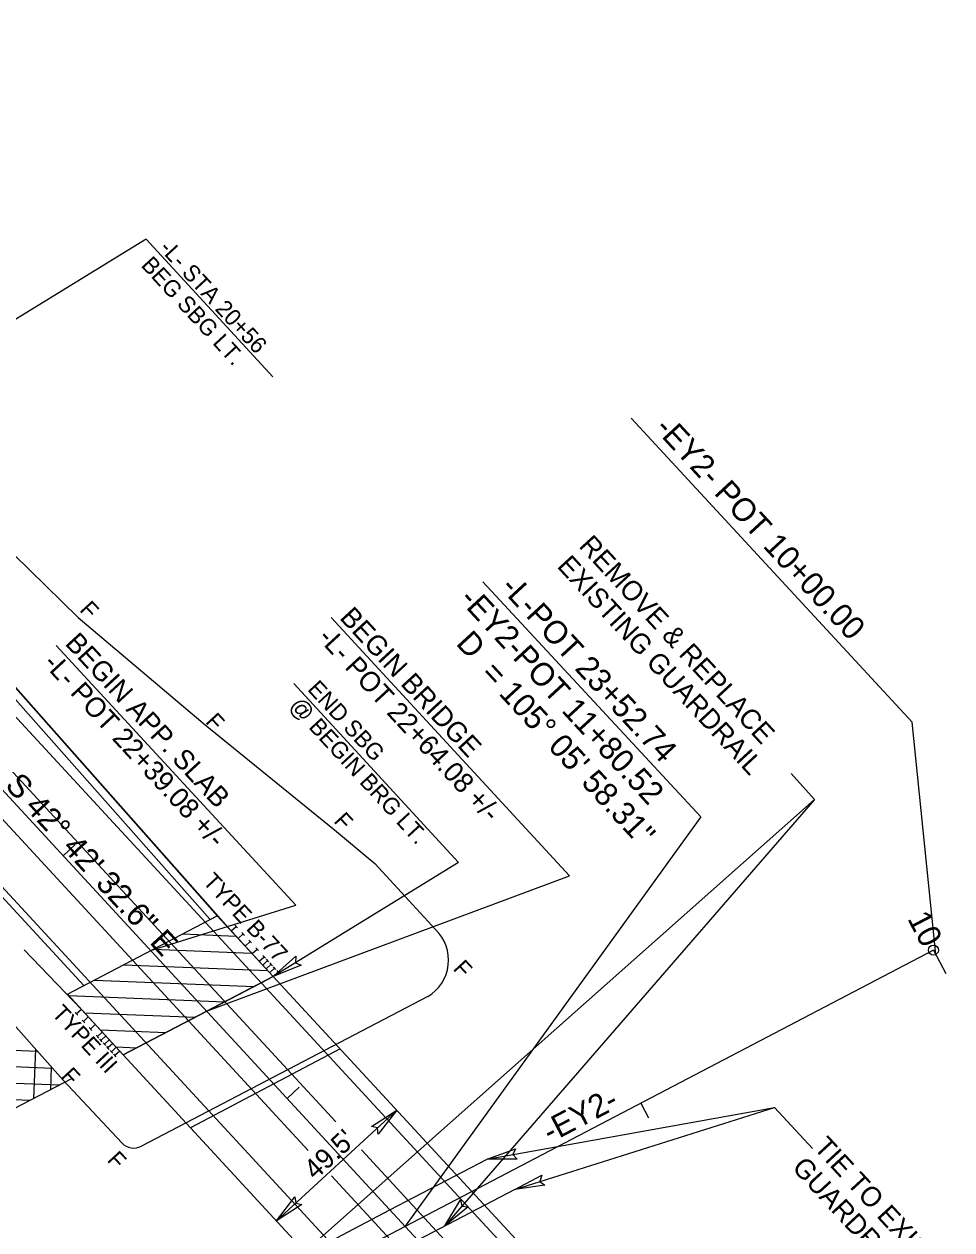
# Model space of a CAD drawing. Extents: x 1702862 to 1704514, y 793768 to 796215.
# Drawn here: x 1703456.2 to 1703737.1, y 794966.9 to 795332.1 of the extents above; entities that cross this region are included whole.
import ezdxf

# ---------------------------------------------------------------- set-up
doc = ezdxf.new("R2010")
doc.units = 0
for name, color, linetype in [('Exist Horizontal Alignment', 7, 'Continuous'), ('Exist Horizontal Alignment Direction Label', 7, 'Continuous'), ('Exist Horizontal Alignment Station Label', 7, 'Continuous'), ('Exist Horizontal Alignment Tick Label', 7, 'Continuous'), ('Exist Horizontal Alignment Tick Large', 7, 'Continuous'), ('Exist Horizontal Alignment Tick Small', 7, 'Continuous'), ('Prop Approach Slab', 7, 'Continuous'), ('Prop Conc 2ft 6in Curb and Gutter', 7, 'Continuous'), ('Prop Conc Shoulder Berm Gutter', 7, 'Continuous'), ('Prop Dimension', 7, 'Continuous'), ('Prop Dimension Text', 7, 'Continuous'), ('Prop DSN Text', 7, 'Continuous'), ('Prop EOT', 7, 'Continuous'), ('Prop Guardrail', 7, 'Continuous'), ('Prop Guardrail Anchor Unit CELL', 7, 'Continuous'), ('Prop Horizontal Alignment', 7, 'Continuous'), ('Prop Horizontal Alignment Direction Label', 7, 'Continuous'), ('Prop Horizontal Alignment Station Label', 7, 'Continuous'), ('Prop Horizontal Alignment Tick Small', 7, 'Continuous'), ('Prop Lane Lines', 7, 'Continuous'), ('Prop Leader Line Medium', 7, 'Continuous'), ('Prop Paved Shoulder', 7, 'Continuous'), ('Prop Rem of Exist Asph Pvmt', 7, 'Continuous'), ('Prop Roadway Bridge', 7, 'Continuous'), ('Prop SS Fill Line', 7, 'Continuous'), ('Prop SS Misc', 7, 'Continuous'), ('Prop Structure Anchor Unit CELL', 7, 'Continuous'), ('Prop Terminator CELL', 7, 'Continuous')]:
    doc.layers.add(name, color=color, linetype=linetype)

msp = doc.modelspace()

# ---------------------------------------------------------------- linework, layer by layer
at = {"layer": 'Exist Horizontal Alignment'}
msp.add_line((1703731.56, 795051.6), (1703391.21, 794873.6), dxfattribs=at)
at = {"layer": 'Exist Horizontal Alignment Station Label'}
for p, q in [((1703595.08, 795163.16), (1703661.15, 795092.04)), ((1703661.15, 795092.04), (1703571.59, 794967.94))]:
    msp.add_line(p, q, dxfattribs=at)
msp.add_lwpolyline([(1703732.26, 795050.27), (1703725.12, 795120.64), (1703640.05, 795212.74)], dxfattribs=at)
msp.add_circle((1703731.56, 795051.6), 1.5, dxfattribs=at)
at = {"layer": 'Exist Horizontal Alignment Tick Large'}
msp.add_line((1703731.56, 795051.6), (1703735.27, 795044.51), dxfattribs=at)
at = {"layer": 'Exist Horizontal Alignment Tick Small'}
msp.add_line((1703642.95, 795005.26), (1703645.26, 795000.83), dxfattribs=at)
at = {"layer": 'Prop Approach Slab'}
for p, q in [((1703469.28, 795038.24), (1703514.68, 795062.03)), ((1703514.68, 795062.03), (1703531.64, 795043.66)), ((1703504.12, 795056.5), (1703520.39, 795055.85)), ((1703495.25, 795051.85), (1703525.19, 795050.65)), ((1703486.37, 795047.2), (1703529.98, 795045.45)), ((1703477.5, 795042.55), (1703525.83, 795040.62)), ((1703486.23, 795019.87), (1703530.26, 795042.94)), ((1703486.23, 795019.87), (1703469.28, 795038.24)), ((1703469.63, 795037.86), (1703516.96, 795035.97)), ((1703474.43, 795032.66), (1703508.08, 795031.32)), ((1703479.22, 795027.47), (1703499.21, 795026.67)), ((1703484.02, 795022.27), (1703490.33, 795022.02))]:
    msp.add_line(p, q, dxfattribs=at)
msp.add_lwpolyline([(1703514.68, 795062.03), (1703531.64, 795043.66), (1703486.23, 795019.87), (1703469.28, 795038.24)], close=True, dxfattribs=at)
at = {"layer": 'Prop Conc 2ft 6in Curb and Gutter'}
msp.add_line((1703417.51, 795102.43), (1703474.32, 795040.89), dxfattribs=at)
at = {"layer": 'Prop Conc Shoulder Berm Gutter'}
msp.add_line((1703389.53, 795203.37), (1703514.68, 795062.03), dxfattribs=at)
at = {"layer": 'Prop Dimension'}
msp.add_line((1703532.64, 794969.6), (1703569.01, 795003.17), dxfattribs=at)
at = {"layer": 'Prop EOT'}
for p, q in [((1703259.9, 795332.15), (1703737.14, 794815.13)), ((1703418.98, 795103.79), (1703631.9, 794873.13))]:
    msp.add_line(p, q, dxfattribs=at)
msp.add_lwpolyline([(1703551.93, 795021.68), (1703506.62, 794997.79)], dxfattribs=at)
at = {"layer": 'Prop Guardrail'}
for p, q in [((1703518.92, 795057.44), (1703389.53, 795203.37)), ((1703456.19, 795051.68), (1703473.52, 795033.65)), ((1703566.95, 794972.97), (1703596.4, 794988.25)), ((1703604.81, 794979.13), (1703575.44, 794963.77)), ((1703492.38, 794933.6), (1703566.95, 794972.97))]:
    msp.add_line(p, q, dxfattribs=at)
at = {"layer": 'Prop Horizontal Alignment'}
msp.add_line((1703246.67, 795319.94), (1703723.92, 794802.92), dxfattribs=at)
at = {"layer": 'Prop Horizontal Alignment Tick Small'}
for p, q in [((1703468, 795080.17), (1703471.67, 795083.56)), ((1703535.82, 795006.69), (1703539.5, 795010.08))]:
    msp.add_line(p, q, dxfattribs=at)
at = {"layer": 'Prop Lane Lines'}
for p, q in [((1703347.89, 795219.14), (1703550.56, 794999.58)), ((1703339.07, 795211), (1703542.22, 794990.92)), ((1703558.4, 794991.09), (1703590.98, 794955.79)), ((1703549.28, 794983.27), (1703583.2, 794946.52))]:
    msp.add_line(p, q, dxfattribs=at)
at = {"layer": 'Prop Leader Line Medium'}
for p, q in [((1703493.18, 795266.98), (1703389.53, 795203.37)), ((1703493.18, 795266.98), (1703531.53, 795225.26)), ((1703549.15, 795152.33), (1703621.31, 795074.15)), ((1703465.86, 795143.9), (1703538.52, 795065.18)), ((1703537.83, 795132.35), (1703587.69, 795078.11)), ((1703695.56, 795097.27), (1703537.91, 794957.38)), ((1703587.69, 795078.11), (1703531.64, 795043.66)), ((1703511.46, 795033.09), (1703621.31, 795074.15)), ((1703494.5, 795051.46), (1703538.52, 795065.18)), ((1703596.4, 794988.25), (1703683.43, 795003.97)), ((1703604.81, 794979.13), (1703683.43, 795003.97)), ((1703683.43, 795003.97), (1703694.94, 794991.5))]:
    msp.add_line(p, q, dxfattribs=at)
msp.add_lwpolyline([(1703688.5, 795105.09), (1703695.56, 795097.27), (1703583.62, 794968.06)], dxfattribs=at)
at = {"layer": 'Prop Paved Shoulder'}
for p, q in [((1703387.81, 795201.79), (1703512.55, 795060.91)), ((1703514.55, 795062.17), (1703531.64, 795043.66))]:
    msp.add_line(p, q, dxfattribs=at)
at = {"layer": 'Prop Rem of Exist Asph Pvmt'}
for p, q in [((1703429.29, 795022.28), (1703460.16, 795021.04)), ((1703459.64, 795021.63), (1703459.04, 795006.69)), ((1703433.84, 795017.09), (1703464.79, 795015.85)), ((1703464.43, 795016.26), (1703464.15, 795009.34)), ((1703438.39, 795011.91), (1703466.9, 795010.77)), ((1703446.88, 795000.39), (1703470.79, 795012.78)), ((1703446.88, 795000.39), (1703470.79, 795012.78)), ((1703442.94, 795006.72), (1703457.94, 795006.12))]:
    msp.add_line(p, q, dxfattribs=at)
at = {"layer": 'Prop Roadway Bridge'}
for p, q in [((1703486.23, 795019.87), (1703531.64, 795043.66)), ((1703531.64, 795043.66), (1703653.75, 794911.37)), ((1703486.23, 795019.87), (1703608.29, 794887.64))]:
    msp.add_line(p, q, dxfattribs=at)
at = {"layer": 'Prop SS Fill Line'}
for p, q in [((1703436.73, 795187.4), (1703472.51, 795152.39)), ((1703472.51, 795152.39), (1703510.99, 795119.86)), ((1703510.99, 795119.86), (1703550.22, 795088.03)), ((1703550.22, 795088.03), (1703562.41, 795077.87)), ((1703562.41, 795077.87), (1703580.79, 795057.85)), ((1703434.77, 795049.5), (1703468.06, 795012.19)), ((1703578.45, 795037.54), (1703491.73, 794992.19)), ((1703468.06, 795012.19), (1703485.76, 794993.21))]:
    msp.add_line(p, q, dxfattribs=at)
for centre, radius, start, end in [((1703571.82, 795048.6), 12.89, 300.952, 45.9027), ((1703489.42, 794996.62), 5, 222.9979, 297.6095)]:
    msp.add_arc(centre, radius, start, end, dxfattribs=at)
at = {"layer": 'Prop Structure Anchor Unit CELL'}
for p, q in [((1703518.92, 795057.44), (1703520.39, 795058.79)), ((1703531.64, 795043.66), (1703518.92, 795057.44)), ((1703520.78, 795058.37), (1703520, 795059.21)), ((1703521.04, 795055.14), (1703522.51, 795056.5)), ((1703522.9, 795056.08), (1703522.12, 795056.92)), ((1703523.16, 795052.84), (1703524.63, 795054.2)), ((1703525.02, 795053.78), (1703524.24, 795054.62)), ((1703525.28, 795050.55), (1703526.75, 795051.9)), ((1703527.14, 795051.48), (1703526.36, 795052.33)), ((1703529.26, 795049.19), (1703528.48, 795050.03)), ((1703527.4, 795048.25), (1703528.87, 795049.61)), ((1703528.46, 795047.1), (1703529.93, 795048.46)), ((1703529.52, 795045.96), (1703530.99, 795047.31)), ((1703530.32, 795048.04), (1703529.54, 795048.88)), ((1703530.58, 795044.81), (1703532.05, 795046.16)), ((1703531.38, 795046.89), (1703530.6, 795047.73)), ((1703532.44, 795045.74), (1703531.66, 795046.58)), ((1703531.64, 795043.66), (1703533.11, 795045.02)), ((1703533.5, 795044.59), (1703532.72, 795045.44)), ((1703472.43, 795031.87), (1703471.66, 795032.71)), ((1703473.52, 795033.65), (1703472.05, 795032.29)), ((1703486.23, 795019.87), (1703473.52, 795033.65)), ((1703474.55, 795029.58), (1703473.78, 795030.42)), ((1703475.63, 795031.35), (1703474.17, 795030)), ((1703476.67, 795027.28), (1703475.9, 795028.12)), ((1703477.75, 795029.06), (1703476.28, 795027.7)), ((1703478.79, 795024.98), (1703478.02, 795025.83)), ((1703479.87, 795026.76), (1703478.4, 795025.4)), ((1703479.85, 795023.84), (1703479.08, 795024.68)), ((1703480.93, 795025.61), (1703479.46, 795024.26)), ((1703481.99, 795024.46), (1703480.52, 795023.11)), ((1703480.91, 795022.69), (1703480.14, 795023.53)), ((1703481.97, 795021.54), (1703481.2, 795022.38)), ((1703483.05, 795023.32), (1703481.58, 795021.96)), ((1703483.03, 795020.39), (1703482.26, 795021.23)), ((1703484.11, 795022.17), (1703482.64, 795020.81)), ((1703485.17, 795021.02), (1703483.7, 795019.66)), ((1703484.09, 795019.24), (1703483.31, 795020.08))]:
    msp.add_line(p, q, dxfattribs=at)
at = {"layer": 'Prop Terminator CELL'}
for points in [[(1703540.13, 795047.04), (1703531.64, 795043.66), (1703538.52, 795049.75), (1703538.38, 795047.79)], [(1703561.35, 794998.21), (1703569.01, 795003.17), (1703563.45, 794995.86), (1703563.21, 794997.81)], [(1703605.53, 794988.32), (1703596.4, 794988.25), (1703605.02, 794991.43), (1703604.17, 794989.65)], [(1703613.86, 794980.37), (1703604.81, 794979.13), (1703612.96, 794983.39), (1703612.34, 794981.51)], [(1703540.3, 794974.56), (1703532.64, 794969.6), (1703538.2, 794976.91), (1703538.44, 794974.96)], [(1703590.68, 794973.84), (1703583.62, 794968.06), (1703588.33, 794975.94), (1703588.79, 794974.03)]]:
    msp.add_lwpolyline(points, close=True, dxfattribs=at)

# ---------------------------------------------------------------- texts
at = {"layer": 'Exist Horizontal Alignment Direction Label'}
msp.add_text('-EY2-', height=7, rotation=27.6095, dxfattribs=at).set_placement((1703615.47, 794993.07))
at = {"layer": 'Exist Horizontal Alignment Station Label'}
msp.add_text('-EY2- POT 10+00.00', height=7, rotation=312.7091, dxfattribs=at).set_placement((1703646.87, 795209.44))
at = {"layer": 'Exist Horizontal Alignment Tick Label'}
msp.add_text('10', height=7, rotation=297.6095, dxfattribs=at).set_placement((1703723.55, 795061.16))
at = {"layer": 'Prop Dimension Text'}
for s, height, rotation, p in [('-L- STA 20+56', 5, 312.7091, (1703496.87, 795264.01)), ('BEG SBG LT.', 5, 312.7091, (1703491.36, 795258.92)), ('REMOVE & REPLACE ', 6, 312.7091, (1703623.93, 795173.87)), ('EXISTING GUARDRAIL', 6, 312.7091, (1703617.32, 795167.76)), ("49.5'", 6, 42.7091, (1703544.33, 794981.76)), ('TIE TO EXIST.', 6, 312.7091, (1703695.07, 794991.61)), ('GUARDRAIL', 6, 312.7091, (1703688.46, 794985.51))]:
    msp.add_text(s, height=height, rotation=rotation, dxfattribs=at).set_placement(p)
at = {"layer": 'Prop DSN Text'}
for s, height, p in [('BEGIN BRIDGE', 6, (1703551.47, 795152.12)), ('BEGIN APP. SLAB', 6, (1703468.32, 795144.34)), ('-L- POT 22+64.08 +/-', 6, (1703544.86, 795146.01)), ('-L- POT 22+39.08 +/-', 6, (1703461.71, 795138.24)), ('END SBG', 5, (1703541.76, 795130.47)), ('@ BEGIN BRG LT.', 5, (1703536.25, 795125.38))]:
    msp.add_text(s, height=height, rotation=312.7091, dxfattribs=at).set_placement(p)
at = {"layer": 'Prop Guardrail Anchor Unit CELL'}
for s, p in [('TYPE B-77', (1703510.07, 795072.15)), ('TYPE III', (1703464.32, 795032.16))]:
    msp.add_text(s, height=5, rotation=312.7301, dxfattribs=at).set_placement(p)
at = {"layer": 'Prop Horizontal Alignment Direction Label'}
msp.add_text('S 42%%d 42\' 32.6" E', height=7, rotation=312.7091, dxfattribs=at).set_placement((1703450.14, 795101.27))
at = {"layer": 'Prop Horizontal Alignment Station Label'}
for s, p in [('-L-POT 23+52.74', (1703600.11, 795161.23)), ('-EY2-POT 11+80.52', (1703587.65, 795157.65)), ('D', (1703586.7, 795144.32)), ('= 105%%d 05\' 58.31"', (1703594.21, 795135.14))]:
    msp.add_text(s, height=7, rotation=312.7091, dxfattribs=at).set_placement(p)
at = {"layer": 'Prop SS Misc'}
for p in [(1703472.76, 795154.54), (1703510.84, 795120.62), (1703549.72, 795090.52), (1703585.84, 795045.79), (1703467.1, 795013.23), (1703481.09, 794987.86)]:
    msp.add_text('F', height=5, rotation=312.7091, dxfattribs=at).set_placement(p)

doc.saveas('drawing.dxf')
